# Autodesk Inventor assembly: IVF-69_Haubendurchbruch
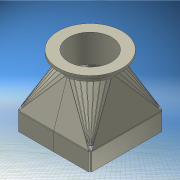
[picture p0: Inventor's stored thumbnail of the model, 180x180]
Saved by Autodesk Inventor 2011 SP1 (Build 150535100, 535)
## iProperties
Created: 2012-03
Part Number: IVF-69_Haubendurchbruch
Document SubType Name: Assembly
Designer: Gawin
Author: Gawin
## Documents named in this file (3)
- F:\IVF-69_Haubendurchbruch\Arbeitsbereich\IVF-69_Haubendurchbruch.iam
- F:\IVF-69_Haubendurchbruch\Arbeitsbereich\IVF-69_Mantelhaelfte_gefraest.ipt
- F:\IVF-69_Haubendurchbruch\Arbeitsbereich\IVF-69_Stutzen.ipt
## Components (3 placed, 2 different names)
1. IVF-69_Stutzen:1 — Fluchtend:3, Fluchtend:4, Fluchtend:5
2. IVF-69_Mantelhaelfte_gefraest:1 — Fluchtend:1, Passend:1, Fluchtend:2
3. IVF-69_Mantelhaelfte_gefraest:2 — Fluchtend:1, Passend:1, Fluchtend:2
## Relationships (6: Flush 5, Mate 1)
- Fluchtend:1 [Flush]: IVF-69_Mantelhaelfte_gefraest:1 ↔ IVF-69_Mantelhaelfte_gefraest:2
- Passend:1 [Mate]: IVF-69_Mantelhaelfte_gefraest:1 ↔ IVF-69_Mantelhaelfte_gefraest:2
- Fluchtend:2 [Flush]: IVF-69_Mantelhaelfte_gefraest:1 ↔ IVF-69_Mantelhaelfte_gefraest:2
- Fluchtend:3 [Flush]: IVF-69_Stutzen:1
- Fluchtend:4 [Flush]: IVF-69_Stutzen:1
- Fluchtend:5 [Flush]: IVF-69_Stutzen:1
